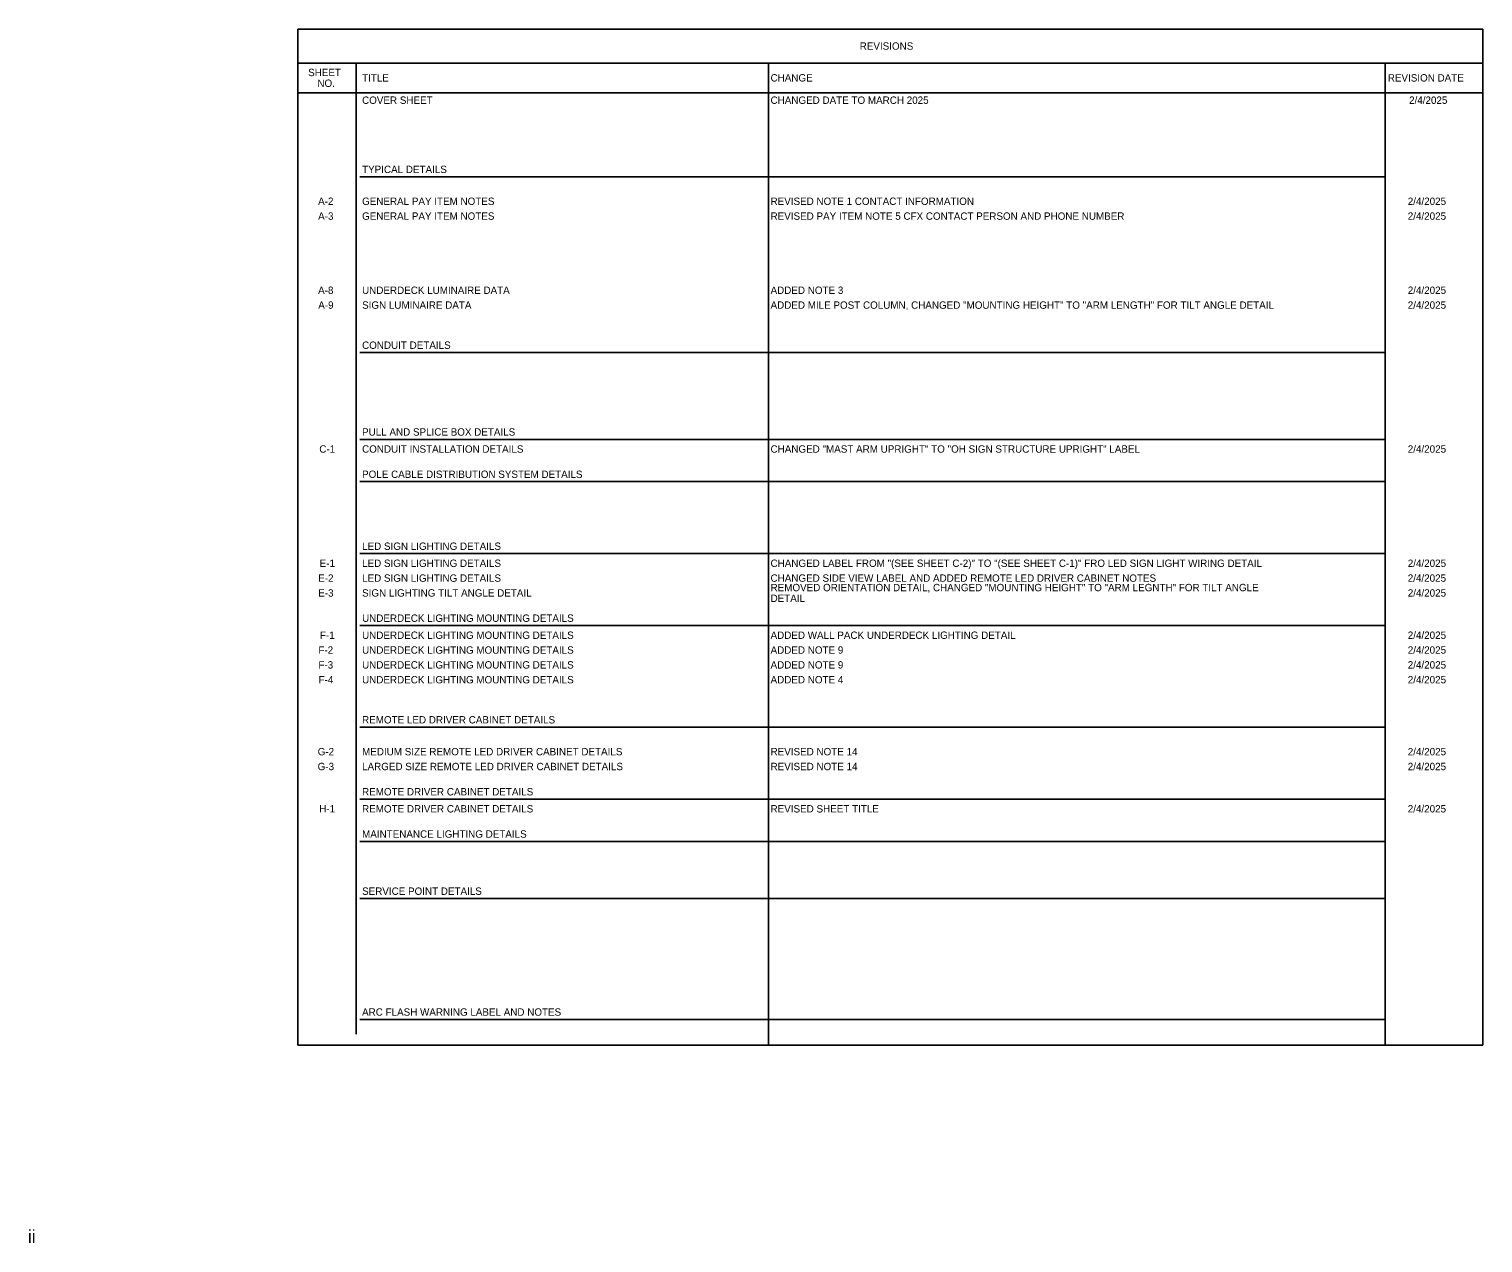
# Model space of a CAD drawing. Extents: x -39 to 1294, y -523 to -44.
# Drawn here: x 735 to 1294, y -511 to -44 of the extents above; entities that cross this region are included whole.
import ezdxf

# ---------------------------------------------------------------- set-up
doc = ezdxf.new("R2010")
doc.units = 0
for name, color, linetype in [('SumBoxLines_dp', 7, 'Continuous'), ('SumBoxLinesMin_dp', 7, 'Continuous'), ('TextLabel', 7, 'Continuous'), ('TextShtNo', 7, 'Continuous')]:
    doc.layers.add(name, color=color, linetype=linetype)

msp = doc.modelspace()

# ---------------------------------------------------------------- linework, layer by layer
at = {"layer": 'SumBoxLines_dp'}
for p, q in [((838.01, -43.57), (1294.4, -43.57)), ((838.01, -43.57), (838.01, -56.62)), ((1294.4, -43.57), (1294.4, -434.55)), ((838.01, -56.62), (1294.4, -56.62)), ((838.01, -56.62), (1294.4, -56.62)), ((860.48, -56.62), (860.48, -257.7)), ((860.48, -56.62), (860.48, -430.42)), ((1019.29, -56.62), (1019.29, -434.55)), ((1256.75, -56.62), (1256.75, -434.55)), ((1256.75, -56.62), (1256.75, -434.55)), ((838.01, -68.04), (1294.4, -68.04)), ((838.01, -68.04), (1294.4, -68.04)), ((862, -100.41), (1256.75, -100.41)), ((862, -100.41), (1256.75, -100.41)), ((862, -168.07), (1256.75, -168.07)), ((862, -168.07), (1256.75, -168.07)), ((862, -201.47), (1256.75, -201.47)), ((862, -201.47), (1256.75, -201.47)), ((862, -217.74), (1256.75, -217.74)), ((862, -217.74), (1256.75, -217.74)), ((862, -245.44), (1256.75, -245.44)), ((862, -245.44), (1256.75, -245.44)), ((860.48, -263.41), (860.48, -419.01)), ((862, -273.13), (1256.75, -273.13)), ((862, -273.13), (1256.75, -273.13)), ((862, -312.24), (1256.75, -312.24)), ((862, -312.24), (1256.75, -312.24)), ((862, -339.93), (1256.75, -339.93)), ((862, -339.93), (1256.75, -339.93)), ((862, -356.21), (1256.75, -356.21)), ((862, -356.21), (1256.75, -356.21)), ((862, -378.2), (1256.75, -378.2)), ((862, -378.2), (1256.75, -378.2)), ((862, -424.72), (1019.29, -424.72)), ((862, -424.72), (1256.75, -424.72))]:
    msp.add_line(p, q, dxfattribs=at)
at = {"layer": 'SumBoxLinesMin_dp'}
for p, q in [((838.01, -56.62), (838.01, -434.55)), ((838.01, -434.55), (1294.4, -434.55))]:
    msp.add_line(p, q, dxfattribs=at)

# ---------------------------------------------------------------- texts
at = {"layer": 'TextLabel'}
for s, height, p in [('REVISIONS', 2.834, (1054.42, -51.51)), ('SHEET', 2.834, (842.04, -61.68)), ('TITLE', 2.834, (862.81, -63.75)), ('CHANGE', 2.834, (1020.1, -63.75)), ('REVISION DATE', 2.8341, (1257.77, -63.75)), ('NO.', 2.834, (845.6, -65.81)), ('COVER SHEET', 2.8341, (862.81, -72.34)), ('CHANGED DATE TO MARCH 2025', 2.8341, (1020.1, -72.34)), ('2/4/2025', 2.834, (1265.97, -72.34)), ('TYPICAL DETAILS', 2.8341, (862.81, -98.97)), ('A-2', 2.834, (845.88, -111.24)), ('GENERAL PAY ITEM NOTES', 2.8341, (862.81, -111.24)), ('REVISED NOTE 1 CONTACT INFORMATION', 2.8341, (1020.1, -111.24)), ('2/4/2025', 2.834, (1265.46, -111.24)), ('A-3', 2.834, (845.88, -116.95)), ('GENERAL PAY ITEM NOTES', 2.8341, (862.81, -116.95)), ('REVISED PAY ITEM NOTE 5 CFX CONTACT PERSON AND PHONE NUMBER', 2.8341, (1020.1, -116.95)), ('2/4/2025', 2.834, (1265.46, -116.95)), ('A-8', 2.834, (845.89, -145.49)), ('UNDERDECK LUMINAIRE DATA', 2.8341, (862.81, -145.49)), ('ADDED NOTE 3', 2.8341, (1020.1, -145.49)), ('2/4/2025', 2.834, (1265.46, -145.49)), ('A-9', 2.834, (845.93, -151.2)), ('SIGN LUMINAIRE DATA', 2.8341, (862.81, -151.2)), ('ADDED MILE POST COLUMN, CHANGED "MOUNTING HEIGHT" TO "ARM LENGTH" FOR TILT ANGLE DETAIL', 2.8341, (1020.1, -151.2)), ('2/4/2025', 2.834, (1265.46, -151.2)), ('CONDUIT DETAILS', 2.8341, (862.81, -166.63)), ('PULL AND SPLICE BOX DETAILS', 2.8341, (862.81, -200.03)), ('C-1', 2.834, (846.34, -206.59)), ('CONDUIT INSTALLATION DETAILS', 2.8341, (862.81, -206.59)), ('CHANGED "MAST ARM UPRIGHT" TO "OH SIGN STRUCTURE UPRIGHT" LABEL', 2.8341, (1020.1, -206.59)), ('2/4/2025', 2.834, (1265.46, -206.59)), ('POLE CABLE DISTRIBUTION SYSTEM DETAILS', 2.8341, (862.81, -216.31)), ('LED SIGN LIGHTING DETAILS', 2.8341, (862.81, -244)), ('E-1', 2.834, (846.48, -250.56)), ('LED SIGN LIGHTING DETAILS', 2.8341, (862.81, -250.56)), ('CHANGED LABEL FROM "(SEE SHEET C-2)" TO "(SEE SHEET C-1)" FRO LED SIGN LIGHT WIRING DETAIL', 2.8341, (1020.1, -250.56)), ('2/4/2025', 2.834, (1265.46, -250.56)), ('E-2', 2.834, (845.91, -256.27)), ('LED SIGN LIGHTING DETAILS', 2.8341, (862.81, -256.27)), ('CHANGED SIDE VIEW LABEL AND ADDED REMOTE LED DRIVER CABINET NOTES', 2.8341, (1020.1, -256.27)), ('REMOVED ORIENTATION DETAIL, CHANGED "MOUNTING HEIGHT" TO "ARM LEGNTH" FOR TILT ANGLE', 2.8341, (1020.1, -259.91)), ('2/4/2025', 2.834, (1265.46, -256.27)), ('E-3', 2.834, (845.91, -261.98)), ('SIGN LIGHTING TILT ANGLE DETAIL', 2.8341, (862.81, -261.98)), ('DETAIL', 2.834, (1020.1, -264.04)), ('2/4/2025', 2.834, (1265.46, -261.98)), ('UNDERDECK LIGHTING MOUNTING DETAILS', 2.8341, (862.81, -271.69)), ('F-1', 2.834, (846.57, -278.25)), ('UNDERDECK LIGHTING MOUNTING DETAILS', 2.8341, (862.81, -278.25)), ('ADDED WALL PACK UNDERDECK LIGHTING DETAIL', 2.8341, (1020.1, -278.25)), ('2/4/2025', 2.834, (1265.46, -278.25)), ('F-2', 2.834, (845.99, -283.96)), ('UNDERDECK LIGHTING MOUNTING DETAILS', 2.8341, (862.81, -283.96)), ('ADDED NOTE 9', 2.8341, (1020.1, -283.96)), ('2/4/2025', 2.834, (1265.46, -283.96)), ('F-3', 2.834, (845.99, -289.67)), ('UNDERDECK LIGHTING MOUNTING DETAILS', 2.8341, (862.81, -289.67)), ('ADDED NOTE 9', 2.8341, (1020.1, -289.67)), ('2/4/2025', 2.834, (1265.46, -289.67)), ('F-4', 2.834, (846.06, -295.38)), ('UNDERDECK LIGHTING MOUNTING DETAILS', 2.8341, (862.81, -295.38)), ('ADDED NOTE 4', 2.8341, (1020.1, -295.38)), ('2/4/2025', 2.834, (1265.46, -295.38)), ('REMOTE LED DRIVER CABINET DETAILS', 2.8341, (862.81, -310.8)), ('G-2', 2.834, (845.71, -323.07)), ('MEDIUM SIZE REMOTE LED DRIVER CABINET DETAILS', 2.8341, (862.81, -323.07)), ('REVISED NOTE 14', 2.8341, (1020.1, -323.07)), ('2/4/2025', 2.834, (1265.46, -323.07)), ('G-3', 2.834, (845.7, -328.78)), ('LARGED SIZE REMOTE LED DRIVER CABINET DETAILS', 2.8341, (862.81, -328.78)), ('REVISED NOTE 14', 2.8341, (1020.1, -328.78)), ('2/4/2025', 2.834, (1265.46, -328.78)), ('REMOTE DRIVER CABINET DETAILS', 2.8341, (862.81, -338.5)), ('H-1', 2.834, (846.3, -345.06)), ('REMOTE DRIVER CABINET DETAILS', 2.8341, (862.81, -345.06)), ('REVISED SHEET TITLE', 2.8341, (1020.1, -345.06)), ('2/4/2025', 2.834, (1265.46, -345.06)), ('MAINTENANCE LIGHTING DETAILS', 2.8341, (862.81, -354.77)), ('SERVICE POINT DETAILS', 2.8341, (862.81, -376.76)), ('ARC FLASH WARNING LABEL AND NOTES', 2.8341, (862.81, -423.28))]:
    msp.add_text(s, height=height, dxfattribs=at).set_placement(p)
at = {"layer": 'TextShtNo'}
msp.add_text('  ii  ', height=5, dxfattribs=at).set_placement((730.42, -510.72))

doc.saveas('drawing.dxf')
